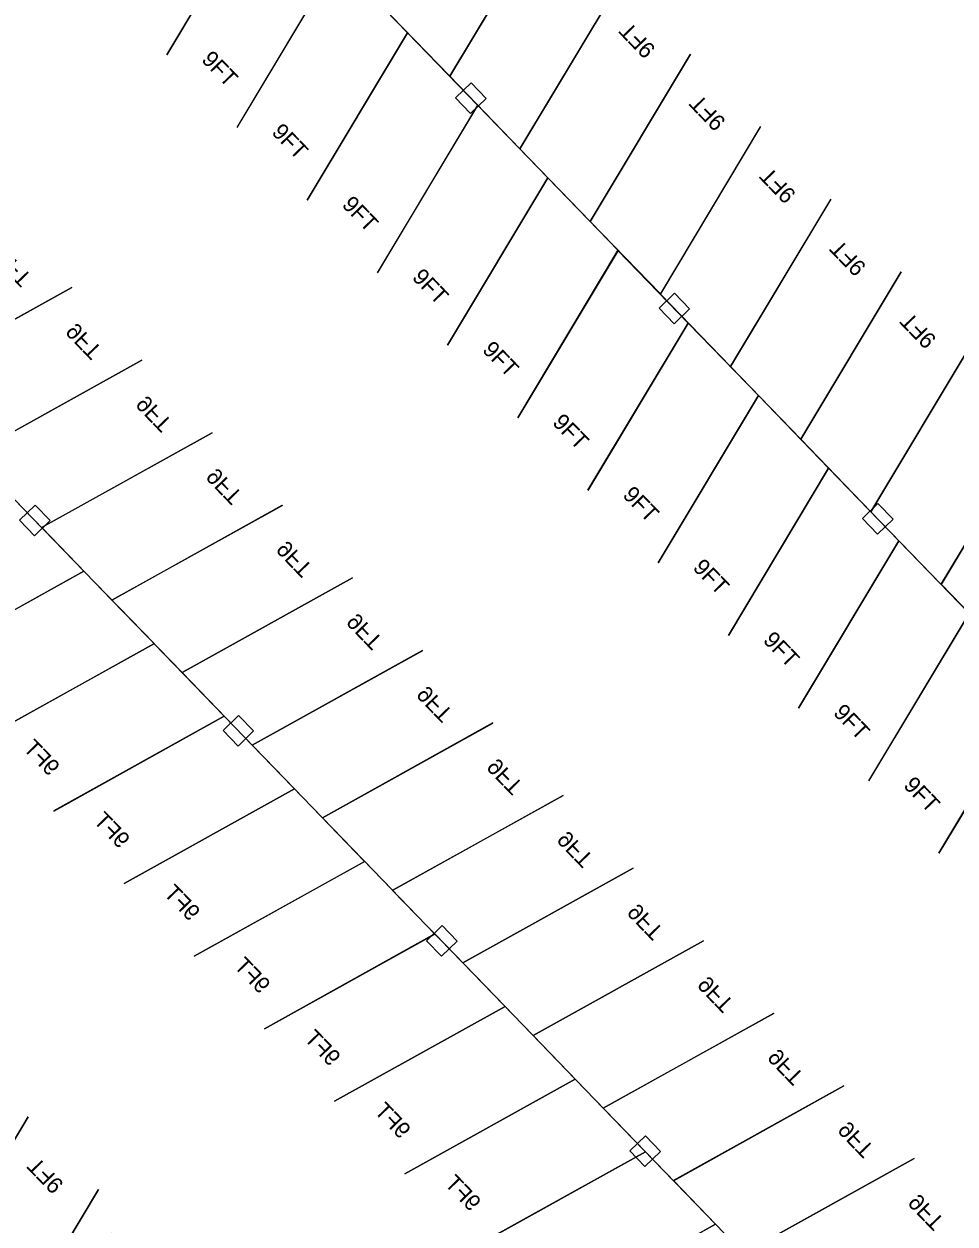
# Model space of a CAD drawing. Extents: x 468143 to 491361, y 1438528 to 1468730.
# Drawn here: x 490416.5 to 490502.4, y 1467509.7 to 1467620.4 of the extents above; entities that cross this region are included whole.
import ezdxf

# ---------------------------------------------------------------- set-up
doc = ezdxf.new("R2010")
doc.units = 0
doc.layers.add('Default', color=7, linetype='Continuous')
doc.layers.add('Xreference_dp', color=7, linetype='Continuous')

# ---------------------------------------------------------------- blocks, each defined once
blk = doc.blocks.new('STALL 9FT-75D')
at = {"layer": 'Default'}
for p, q in [((0, 0), (111.8, 0)), ((111.8, 0), (167.7, -208.6))]:
    blk.add_line(p, q, dxfattribs=at)
blk.add_lwpolyline([(55.9, -208.6), (0, 0)], dxfattribs=at)
blk.add_text('9FT', height=18, dxfattribs=at).set_placement((86.4, -185.9))
blk = doc.blocks.new('Col 24x24')
at = {"layer": 'Default'}
blk.add_lwpolyline([(-11.999976, -11.999976), (-11.999976, 11.999976), (11.999976, 11.999976), (11.999976, -11.999976), (-11.999976, -11.999976)], dxfattribs=at)
blk.add_lwpolyline([(-11.999976, -11.999976), (11.999976, -11.999976), (11.999976, 11.999976), (-11.999976, 11.999976)], close=True, dxfattribs=at)

msp = doc.modelspace()

# ---------------------------------------------------------------- block references
at = {"layer": 'Xreference_dp'}
for name, p, xscale, yscale, rotation in [('STALL 9FT-75D', (490432.41, 1467639.65), 0.08333072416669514, 0.08333072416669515, -45.942932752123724), ('STALL 9FT-75D', (490432.41, 1467639.65), 0.08333072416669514, 0.08333072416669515, -45.942932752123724), ('STALL 9FT-75D', (490455.76, 1467615.54), 0.0833307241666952, 0.08333072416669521, 134.05706724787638), ('STALL 9FT-75D', (490455.76, 1467615.54), 0.0833307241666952, 0.08333072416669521, 134.05706724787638), ('STALL 9FT-75D', (490521.97, 1467627.76), 0.08333072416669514, -0.08333072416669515, 134.0570672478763), ('STALL 9FT-75D', (490521.97, 1467627.76), 0.08333072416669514, -0.08333072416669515, 134.0570672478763), ('STALL 9FT-75D', (490438.89, 1467632.95), 0.08333072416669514, 0.08333072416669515, -45.942932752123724), ('STALL 9FT-75D', (490438.89, 1467632.95), 0.08333072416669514, 0.08333072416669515, -45.942932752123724), ('STALL 9FT-75D', (490462.23, 1467608.85), 0.0833307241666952, 0.08333072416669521, 134.05706724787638), ('STALL 9FT-75D', (490462.23, 1467608.85), 0.0833307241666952, 0.08333072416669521, 134.05706724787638), ('STALL 9FT-75D', (490445.37, 1467626.25), 0.08333072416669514, 0.08333072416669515, -45.942932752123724), ('STALL 9FT-75D', (490445.37, 1467626.25), 0.08333072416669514, 0.08333072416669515, -45.942932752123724), ('STALL 9FT-75D', (490468.71, 1467602.15), 0.0833307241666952, 0.08333072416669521, 134.05706724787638), ('STALL 9FT-75D', (490468.71, 1467602.15), 0.0833307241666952, 0.08333072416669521, 134.05706724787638), ('STALL 9FT-75D', (490451.85, 1467619.56), 0.08333072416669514, 0.08333072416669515, -45.942932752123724), ('STALL 9FT-75D', (490451.85, 1467619.56), 0.08333072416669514, 0.08333072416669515, -45.942932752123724), ('STALL 9FT-75D', (490475.19, 1467595.46), 0.0833307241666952, 0.08333072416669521, 134.05706724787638), ('STALL 9FT-75D', (490475.19, 1467595.46), 0.0833307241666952, 0.08333072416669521, 134.05706724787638), ('Col 24x24', (490457.7, 1467613.52), 0.0833307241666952, 0.0833307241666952, 44.062944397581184), ('Col 24x24', (490457.7, 1467613.52), 0.0833307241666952, 0.0833307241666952, 44.062944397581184), ('STALL 9FT-75D', (490458.33, 1467612.86), 0.08333072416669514, 0.08333072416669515, -45.942932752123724), ('STALL 9FT-75D', (490458.33, 1467612.86), 0.08333072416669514, 0.08333072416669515, -45.942932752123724), ('STALL 9FT-75D', (490481.67, 1467588.76), 0.0833307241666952, 0.08333072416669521, 134.05706724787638), ('STALL 9FT-75D', (490481.67, 1467588.76), 0.0833307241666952, 0.08333072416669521, 134.05706724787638), ('STALL 9FT-75D', (490398.65, 1467594.01), 0.0833307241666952, -0.0833307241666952, -45.94293275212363), ('STALL 9FT-75D', (490398.65, 1467594.01), 0.0833307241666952, -0.0833307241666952, -45.94293275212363), ('STALL 9FT-75D', (490464.81, 1467606.17), 0.08333072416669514, 0.08333072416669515, -45.942932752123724), ('STALL 9FT-75D', (490464.81, 1467606.17), 0.08333072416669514, 0.08333072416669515, -45.942932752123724), ('STALL 9FT-75D', (490488.15, 1467582.06), 0.0833307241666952, 0.08333072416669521, 134.05706724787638), ('STALL 9FT-75D', (490488.15, 1467582.06), 0.0833307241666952, 0.08333072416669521, 134.05706724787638), ('STALL 9FT-75D', (490405.13, 1467587.31), 0.0833307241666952, -0.0833307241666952, -45.94293275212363), ('STALL 9FT-75D', (490405.13, 1467587.31), 0.0833307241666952, -0.0833307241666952, -45.94293275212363), ('STALL 9FT-75D', (490471.28, 1467599.47), 0.08333072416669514, 0.08333072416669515, -45.942932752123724), ('STALL 9FT-75D', (490471.28, 1467599.47), 0.08333072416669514, 0.08333072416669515, -45.942932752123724), ('STALL 9FT-75D', (490494.63, 1467575.37), 0.0833307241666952, 0.08333072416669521, 134.05706724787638), ('STALL 9FT-75D', (490494.63, 1467575.37), 0.0833307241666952, 0.08333072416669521, 134.05706724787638), ('Col 24x24', (490476.48, 1467594.12), 0.0833307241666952, 0.0833307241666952, 44.062944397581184), ('Col 24x24', (490476.48, 1467594.12), 0.0833307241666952, 0.0833307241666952, 44.062944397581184), ('STALL 9FT-75D', (490411.61, 1467580.61), 0.0833307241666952, -0.0833307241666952, -45.94293275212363), ('STALL 9FT-75D', (490411.61, 1467580.61), 0.0833307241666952, -0.0833307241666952, -45.94293275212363), ('STALL 9FT-75D', (490477.76, 1467592.78), 0.08333072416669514, 0.08333072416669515, -45.942932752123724), ('STALL 9FT-75D', (490477.76, 1467592.78), 0.08333072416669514, 0.08333072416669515, -45.942932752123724), ('STALL 9FT-75D', (490501.11, 1467568.67), 0.0833307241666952, 0.08333072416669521, 134.05706724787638), ('STALL 9FT-75D', (490501.11, 1467568.67), 0.0833307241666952, 0.08333072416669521, 134.05706724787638), ('STALL 9FT-75D', (490418.09, 1467573.92), 0.0833307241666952, -0.0833307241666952, -45.94293275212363), ('STALL 9FT-75D', (490418.09, 1467573.92), 0.0833307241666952, -0.0833307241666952, -45.94293275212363), ('STALL 9FT-75D', (490484.24, 1467586.08), 0.08333072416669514, 0.08333072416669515, -45.942932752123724), ('STALL 9FT-75D', (490484.24, 1467586.08), 0.08333072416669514, 0.08333072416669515, -45.942932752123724), ('STALL 9FT-75D', (490507.59, 1467561.98), 0.0833307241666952, 0.08333072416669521, 134.05706724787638), ('STALL 9FT-75D', (490507.59, 1467561.98), 0.0833307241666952, 0.08333072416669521, 134.05706724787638), ('STALL 9FT-75D', (490421.98, 1467569.89), 0.08333072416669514, -0.08333072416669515, 134.0570672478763), ('STALL 9FT-75D', (490421.98, 1467569.89), 0.08333072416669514, -0.08333072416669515, 134.0570672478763), ('STALL 9FT-75D', (490424.57, 1467567.22), 0.0833307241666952, -0.0833307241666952, -45.94293275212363), ('STALL 9FT-75D', (490424.57, 1467567.22), 0.0833307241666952, -0.0833307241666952, -45.94293275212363), ('STALL 9FT-75D', (490490.72, 1467579.38), 0.08333072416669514, 0.08333072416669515, -45.942932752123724), ('STALL 9FT-75D', (490490.72, 1467579.38), 0.08333072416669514, 0.08333072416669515, -45.942932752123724), ('Col 24x24', (490417.46, 1467574.57), 0.0833307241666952, 0.0833307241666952, 44.062944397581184), ('Col 24x24', (490417.46, 1467574.57), 0.0833307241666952, 0.0833307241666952, 44.062944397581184), ('Col 24x24', (490495.25, 1467574.71), 0.0833307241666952, 0.0833307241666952, 44.062944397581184), ('Col 24x24', (490495.25, 1467574.71), 0.0833307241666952, 0.0833307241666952, 44.062944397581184), ('STALL 9FT-75D', (490428.46, 1467563.2), 0.08333072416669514, -0.08333072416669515, 134.0570672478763), ('STALL 9FT-75D', (490428.46, 1467563.2), 0.08333072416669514, -0.08333072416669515, 134.0570672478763), ('STALL 9FT-75D', (490431.05, 1467560.53), 0.0833307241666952, -0.0833307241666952, -45.94293275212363), ('STALL 9FT-75D', (490431.05, 1467560.53), 0.0833307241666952, -0.0833307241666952, -45.94293275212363), ('STALL 9FT-75D', (490497.2, 1467572.69), 0.08333072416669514, 0.08333072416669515, -45.942932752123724), ('STALL 9FT-75D', (490497.2, 1467572.69), 0.08333072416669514, 0.08333072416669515, -45.942932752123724), ('STALL 9FT-75D', (490434.94, 1467556.5), 0.08333072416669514, -0.08333072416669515, 134.0570672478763), ('STALL 9FT-75D', (490434.94, 1467556.5), 0.08333072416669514, -0.08333072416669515, 134.0570672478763), ('STALL 9FT-75D', (490437.52, 1467553.83), 0.0833307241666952, -0.0833307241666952, -45.94293275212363), ('STALL 9FT-75D', (490437.52, 1467553.83), 0.0833307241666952, -0.0833307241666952, -45.94293275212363), ('STALL 9FT-75D', (490503.68, 1467565.99), 0.08333072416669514, 0.08333072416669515, -45.942932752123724), ('STALL 9FT-75D', (490503.68, 1467565.99), 0.08333072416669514, 0.08333072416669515, -45.942932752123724), ('STALL 9FT-75D', (490441.42, 1467549.81), 0.08333072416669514, -0.08333072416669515, 134.0570672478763), ('STALL 9FT-75D', (490441.42, 1467549.81), 0.08333072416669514, -0.08333072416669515, 134.0570672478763), ('STALL 9FT-75D', (490444, 1467547.14), 0.0833307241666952, -0.0833307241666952, -45.94293275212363), ('STALL 9FT-75D', (490444, 1467547.14), 0.0833307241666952, -0.0833307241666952, -45.94293275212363), ('STALL 9FT-75D', (490510.16, 1467559.3), 0.08333072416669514, 0.08333072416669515, -45.942932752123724), ('STALL 9FT-75D', (490510.16, 1467559.3), 0.08333072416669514, 0.08333072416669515, -45.942932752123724), ('Col 24x24', (490436.24, 1467555.17), 0.0833307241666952, 0.0833307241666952, 44.062944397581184), ('Col 24x24', (490436.24, 1467555.17), 0.0833307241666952, 0.0833307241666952, 44.062944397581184), ('STALL 9FT-75D', (490447.9, 1467543.11), 0.08333072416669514, -0.08333072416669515, 134.0570672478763), ('STALL 9FT-75D', (490447.9, 1467543.11), 0.08333072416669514, -0.08333072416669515, 134.0570672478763), ('STALL 9FT-75D', (490450.48, 1467540.44), 0.0833307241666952, -0.0833307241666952, -45.94293275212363), ('STALL 9FT-75D', (490450.48, 1467540.44), 0.0833307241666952, -0.0833307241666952, -45.94293275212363), ('STALL 9FT-75D', (490454.38, 1467536.41), 0.08333072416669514, -0.08333072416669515, 134.0570672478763), ('STALL 9FT-75D', (490454.38, 1467536.41), 0.08333072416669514, -0.08333072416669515, 134.0570672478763), ('STALL 9FT-75D', (490456.96, 1467533.74), 0.0833307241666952, -0.0833307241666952, -45.94293275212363), ('STALL 9FT-75D', (490456.96, 1467533.74), 0.0833307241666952, -0.0833307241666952, -45.94293275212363), ('STALL 9FT-75D', (490460.86, 1467529.72), 0.08333072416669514, -0.08333072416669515, 134.0570672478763), ('STALL 9FT-75D', (490460.86, 1467529.72), 0.08333072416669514, -0.08333072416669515, 134.0570672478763), ('STALL 9FT-75D', (490463.44, 1467527.05), 0.0833307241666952, -0.0833307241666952, -45.94293275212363), ('STALL 9FT-75D', (490463.44, 1467527.05), 0.0833307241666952, -0.0833307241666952, -45.94293275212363), ('Col 24x24', (490455.02, 1467535.77), 0.0833307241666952, 0.0833307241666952, 44.062944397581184), ('Col 24x24', (490455.02, 1467535.77), 0.0833307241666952, 0.0833307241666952, 44.062944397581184), ('STALL 9FT-75D', (490467.34, 1467523.02), 0.08333072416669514, -0.08333072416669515, 134.0570672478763), ('STALL 9FT-75D', (490467.34, 1467523.02), 0.08333072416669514, -0.08333072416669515, 134.0570672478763), ('STALL 9FT-75D', (490469.92, 1467520.35), 0.0833307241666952, -0.0833307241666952, -45.94293275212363), ('STALL 9FT-75D', (490469.92, 1467520.35), 0.0833307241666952, -0.0833307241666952, -45.94293275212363), ('STALL 9FT-75D', (490407.6, 1467504.11), 0.0833307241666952, 0.08333072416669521, 134.05706724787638), ('STALL 9FT-75D', (490407.6, 1467504.11), 0.0833307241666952, 0.08333072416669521, 134.05706724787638), ('STALL 9FT-75D', (490473.82, 1467516.33), 0.08333072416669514, -0.08333072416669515, 134.0570672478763), ('STALL 9FT-75D', (490473.82, 1467516.33), 0.08333072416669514, -0.08333072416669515, 134.0570672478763), ('STALL 9FT-75D', (490476.4, 1467513.66), 0.0833307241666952, -0.0833307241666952, -45.94293275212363), ('STALL 9FT-75D', (490476.4, 1467513.66), 0.0833307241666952, -0.0833307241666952, -45.94293275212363), ('STALL 9FT-75D', (490414.08, 1467497.41), 0.0833307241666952, 0.08333072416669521, 134.05706724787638), ('STALL 9FT-75D', (490414.08, 1467497.41), 0.0833307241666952, 0.08333072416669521, 134.05706724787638), ('STALL 9FT-75D', (490480.29, 1467509.63), 0.08333072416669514, -0.08333072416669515, 134.0570672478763), ('STALL 9FT-75D', (490480.29, 1467509.63), 0.08333072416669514, -0.08333072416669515, 134.0570672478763), ('STALL 9FT-75D', (490482.88, 1467506.96), 0.0833307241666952, -0.0833307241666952, -45.94293275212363), ('STALL 9FT-75D', (490482.88, 1467506.96), 0.0833307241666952, -0.0833307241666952, -45.94293275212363), ('Col 24x24', (490473.79, 1467516.37), 0.0833307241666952, 0.0833307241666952, 44.062944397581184), ('Col 24x24', (490473.79, 1467516.37), 0.0833307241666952, 0.0833307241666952, 44.062944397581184), ('STALL 9FT-75D', (490420.56, 1467490.72), 0.0833307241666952, 0.08333072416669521, 134.05706724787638), ('STALL 9FT-75D', (490420.56, 1467490.72), 0.0833307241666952, 0.08333072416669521, 134.05706724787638), ('STALL 9FT-75D', (490486.77, 1467502.94), 0.08333072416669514, -0.08333072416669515, 134.0570672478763), ('STALL 9FT-75D', (490486.77, 1467502.94), 0.08333072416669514, -0.08333072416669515, 134.0570672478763)]:
    msp.add_blockref(name, p, dxfattribs=dict(at, xscale=xscale, yscale=yscale, rotation=rotation))

doc.saveas('drawing.dxf')
